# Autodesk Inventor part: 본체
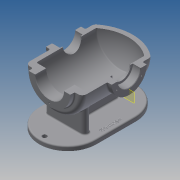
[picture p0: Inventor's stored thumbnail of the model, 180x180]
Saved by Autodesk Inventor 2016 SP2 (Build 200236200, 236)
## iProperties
Created: 2016-02
Part Number: 본체
Material: 알루미늄 6061
Document SubType Name: Modeling
Designer: mduedu
Density: 2.71 g/cm^3
Mass: 2160.77 g
Surface Area: 1521.78 cm^2
Volume: 797.331 cm^3
Appearance: 기본값
Author: mduedu
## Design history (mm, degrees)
sketch "스케치2"
  geometry: L1 (0, 90)-(0, -90); L2 (65, -65.993)-(65, 90); L3 (65, 90)-(0, 90); A1 r 100 centre (0, 10) between (0, -90) and (65, -65.993); 2 further points
  constraints: 6 end point, 2 point on circle, 1 centre point, 1 coincident, 1 horizontal, 1 midpoint, 1 parallel, 1 point on line, 1 vertical
  dimensions: "d3" = 180 distance of L1.start L1.end; "d5" = 130 diameter of L2 L1; "d6" = 100 radius of A1
revolve "회전1" sketch "스케치2" stored, may be unused: angle "d7" = 90 deg
sketch "스케치3"
  geometry: C1 r 47.5 at (0, 0); 1 further point
  constraints: 1 centre point, 1 coincident
  dimensions: "d8" = 95 diameter of C1
extrude "돌출2" join sketch "스케치3" distance "d10" = 10; taper "d11" = 0 deg
sketch "스케치5"
  geometry: L1 (47.5, 100)-(47.5, 90) reference; L2 (47.5, 90)-(65, 90) reference; L3 (65, 90)-(65, -65.993) reference; L4 (-65, -65.993)-(-65, 90) reference; L5 (-65, 90)-(-47.5, 90) reference; L6 (-47.5, 90)-(-47.5, 100) reference; L7 (-47.5, 100)-(47.5, 100) reference; L8 (55, 75)-(55, -61.239); L9 (0, 75)-(55, 75); L10 (0, 75)-(0, -80); A1 r 100 centre (0, 10) between (-65, -65.993) and (0, -90) reference; A2 r 100 centre (0, 10) between (0, -90) and (65, -65.993) reference; A3 r 90 centre (0, 10) between (0, -80) and (55, -61.239); 1 further point
  constraints: 6 end point, 2 point on circle, 1 centre point, 1 parallel, 1 perpendicular, 1 point on line, 1 vertical
  dimensions: "d13" = 10 distance between parallel lines of L3 L8; "d14" = 10 radial gap between concentric circles of A3 A1; "d15" = 15 distance between parallel lines of L9 L2
revolve "회전2" sketch "스케치5" stored, may be unused: angle "d16" = 90 deg
hole "구멍1" diameter "d19" = 65; stored, may be unused: countersink angle "d23" = 90 deg, drill point angle "d25" = 118 deg; dims "d17" = 10, "d18" = 10, "d20" = 6, "d21" = 4, "d22" = 2, "d24" = 8
node "작업 평면1"
sketch "스케치6"
  geometry: L1 (47.5, 100)-(-47.5, 100) reference; C1 r 40 at (0, -7); 1 further point
  constraints: 1 centre point, 1 vertical alignment
  dimensions: "d27" = 80 diameter of C1; "d29" = 107 distance from line of C1.centre L1
extrude "돌출3" join sketch "스케치6" stored distance "d30" = 10; taper "d31" = 0 deg
hole "구멍2" diameter "d34" = 42; stored, may be unused: countersink angle "d38" = 90 deg, drill point angle "d40" = 118 deg; dims "d32" = 10, "d33" = 10, "d35" = 6, "d36" = 52, "d37" = 18, "d39" = 8
sketch "스케치7" dims "d41" = 65
  geometry: C1 r 40 at (0, 0) reference; 3 further points
  constraints: 2 vertical alignment, 1 coincident, 2 other
hole "구멍3" sketch "스케치7" at (0, 32.5) diameter "d43" = 3.242; stored, may be unused: countersink angle "d47" = 90 deg, drill point angle "d49" = 118 deg; dims "d44" = 11, "d45" = 13, "d46" = 18, "d48" = 13
sketch "스케치8" dims "d53" = 80
  geometry: 3 further points
  constraints: 2 vertical alignment, 1 coincident, 2 other
hole "구멍4" sketch "스케치8" at (0, -40) diameter "d56" = 3.242; stored, may be unused: countersink angle "d60" = 90 deg, drill point angle "d62" = 118 deg; dims "d57" = 11, "d58" = 13, "d59" = 18, "d61" = 13
fillet "모깎기1" dims "d66" = 10
fillet "모깎기2" dims "d67" = 3
fillet "모깎기3" dims "d68" = 1
chamfer "모따기1" distance "d69" = 1; stored, may be unused: second distance "d70" = 2, angle "d71" = 45 deg
node "작업 평면5"
sketch "스케치10"
  geometry: L1 (-45, 66)-(45, 66); L2 (45, 66)-(45, 50); L3 (45, 50)-(-45, 50); L4 (-45, 50)-(-45, 66); 2 further points
  constraints: 8 end point, 2 horizontal, 2 vertical, 1 midpoint, 1 vertical alignment
  dimensions: "d177" = 50 distance from line of L3 point (0, 0); "d178" = 90 distance of L1.start L1.end; "d179" = 16 distance of L3.end L1.start
extrude "돌출5" join sketch "스케치10" stored distance "d84" = 10; taper "d85" = 0 deg
sketch "스케치21" dims "d180" = 220, "d182" = 130
  geometry: L1 (65, 58)-(-65, 58); L2 (-65, 58)-(-65, -32); L3 (-65, -32)-(65, -32); L4 (65, -32)-(65, 58); L5 (45, 50)-(45, 66) reference; 4 further points
  constraints: 8 end point, 3 horizontal alignment, 3 midpoint, 2 parallel, 1 horizontal, 1 perpendicular, 1 vertical alignment, 4 other
extrude "돌출13" join sketch "스케치21" distance "d183" = 10; taper "d184" = 0 deg
sketch "스케치11"
  geometry: L1 (-65, 80)-(-65, -61.239) reference; L2 (-100, -97)-(-100, -32) reference; L3 (-65, -45.829)-(-100, -52); L4 (-100, -97)-(-110, -97) reference; 1 further point
  constraints: 2 end point, 2 point on line
  dimensions: "d185" = 45 distance from line of L3.end L4; "d186" = 100 deg angle of L2 L3
feature "리브1" sketch "스케치11" dims "d88" = 1, "d89" = 16, "d90" = 0, "d91" = 0, "d92" = 1, "d93" = 1
fillet "모깎기12"
fillet "모깎기13"
fillet "모깎기16" dims "d167" = 3
fillet "모깎기18"
fillet "모깎기17" dims "d168" = 3
fillet "모깎기19" dims "d187" = 3
node "작업 평면6"
sketch "스케치19"
  geometry: L1 (75, -47)-(75, 33) reference; L2 (-75, -47)-(-75, 33) reference; L3 (75, -7)-(-75, -7); C1 r 22.5 at (0, -7); 1 further point
  constraints: 3 midpoint, 2 end point, 1 centre point
  dimensions: "d149" = 45 diameter of C1
extrude "돌출11" join sketch "스케치19" stored distance "d150" = 10; taper "d151" = 0 deg
hole "구멍6" diameter "d154" = 33.376; stored, may be unused: countersink angle "d158" = 90 deg, drill point angle "d160" = 118 deg; dims "d155" = 6, "d156" = 4, "d157" = 2, "d159" = 8, "d190" = 10, "d191" = 10
fillet "모깎기11" dims "d161" = 3
chamfer "모따기3" distance "d164" = 1; stored, may be unused: second distance "d165" = 2, angle "d166" = 45 deg
node "작업 평면9"
  node "작업 평면8"
sketch "스케치22"
  geometry: L1 (-65, -58)-(-65, 32) reference; L2 (65, 32)-(65, -58) reference; L3 (53, 32)-(53, -58); L4 (-53, -58)-(-53, 32); C1 r 5 at (0, -111); A1 r 65 centre (0, -58) between (-65, -58) and (65, -58) reference; A2 r 65 centre (0, 32) between (65, 32) and (-65, 32) reference; A3 r 53 centre (0, 32) between (53, 32) and (-53, 32); A4 r 53 centre (0, -58) between (-53, -58) and (53, -58); 1 further point
  constraints: 5 point on circle, 4 end point, 3 centre point, 3 other
  dimensions: "d201" = 12 distance between parallel lines of L3 L2; "d202" = 10 diameter of C1
extrude "돌출14" cut sketch "스케치22" stored distance "d194" = 10; taper "d195" = 0 deg
fillet "모깎기21" dims "d196" = 3
feature "분할1"
sketch "스케치23"
  geometry: L1 (-65, 32)-(-65, -58) reference; L2 (65, -58)-(65, 32) reference; L3 (-65, -13)-(65, -13); 2 further points
  constraints: 2 end point, 2 midpoint, 1 point on line, 1 other
  dimensions: "d197" = 12 distance from line of point (53, -13) L2
feature "엠보싱2" sketch "스케치23" dims "d3" = 180, "d5" = 130, "d6" = 100, "d198" = 0.5, "d199" = 0
node "작업 평면10"
node "솔리드2"
pattern_circular "원형 패턴1" dims angle "d51" = 360 deg
mirror "대칭1"
pattern_circular "원형 패턴2" dims angle "d64" = 360 deg
mirror "대칭3"
node "절단 모서리 투영1"
other parameters: "d26" = 75, "d136" = 175
